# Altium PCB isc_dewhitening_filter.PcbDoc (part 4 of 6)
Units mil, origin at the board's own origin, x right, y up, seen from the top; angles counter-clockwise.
Board outline 8440 x 7000 mil, 6 copper layers (Top Layer, MidLayer1, InternalPlane1, Internal Plane 3, InternalPlane2, Bottom Layer); 550 components, 462 nets, 2189 pads, 795 vias.
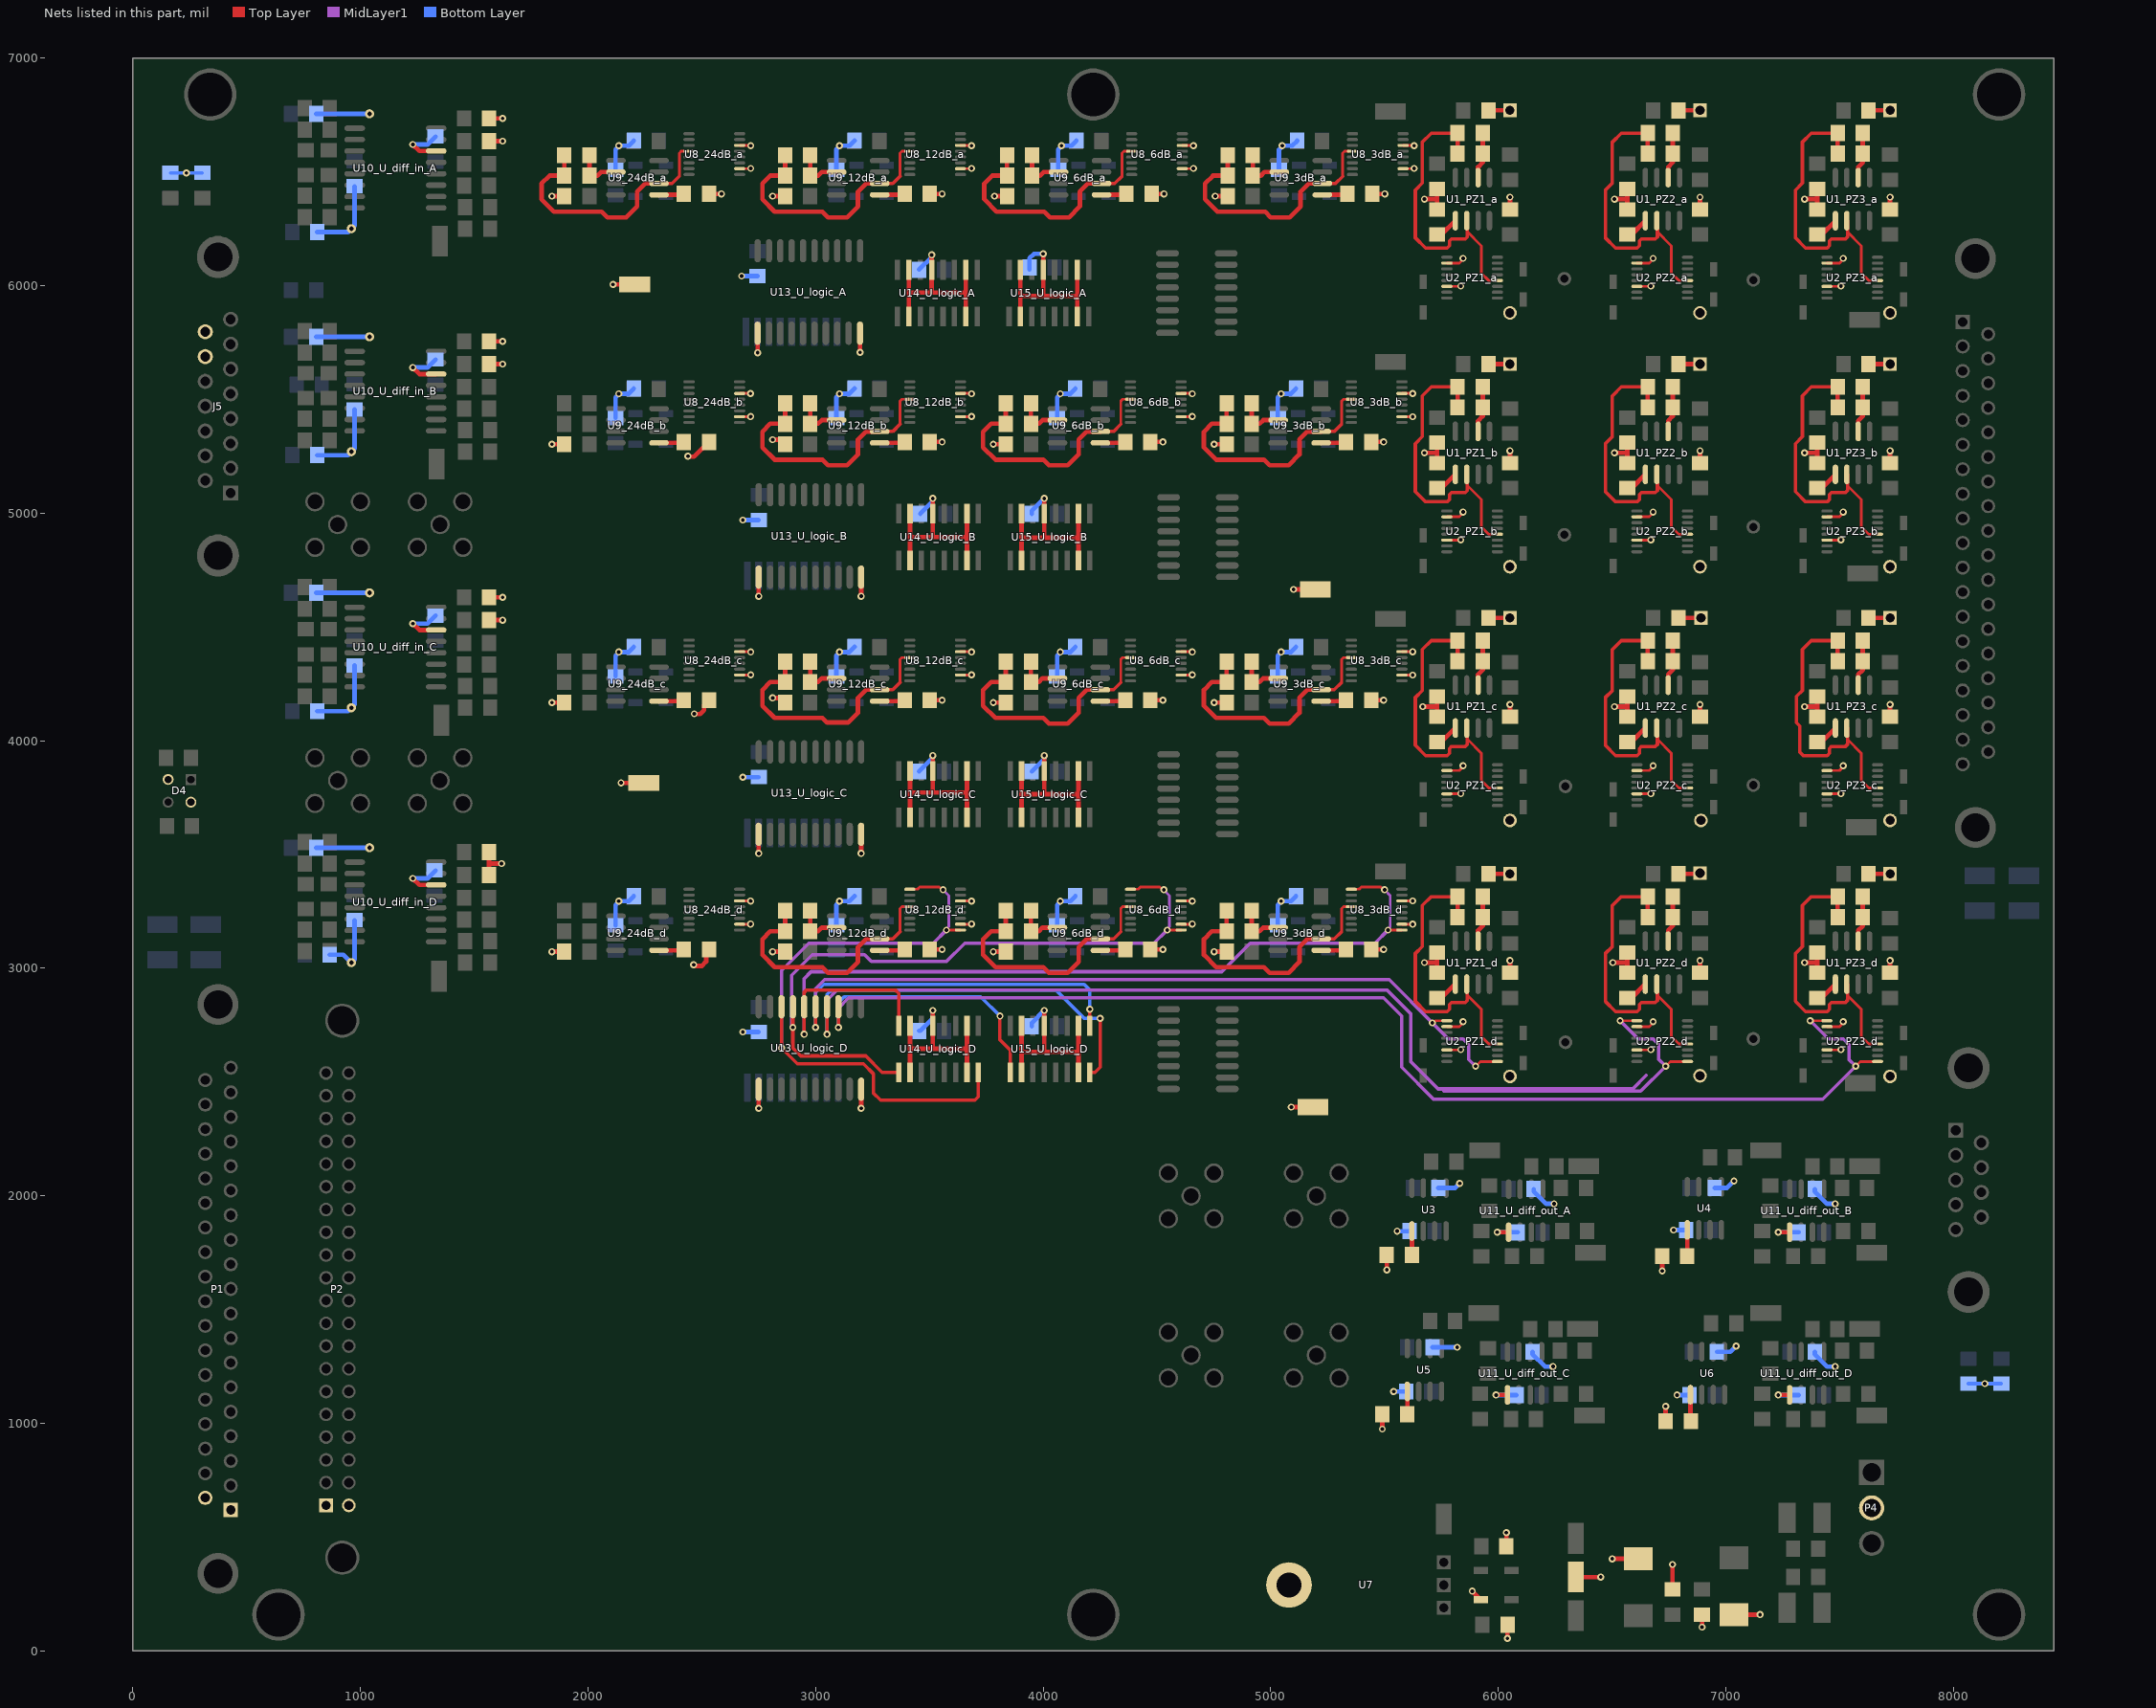
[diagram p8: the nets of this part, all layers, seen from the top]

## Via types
v1: diameter 31, hole 16, Top Layer to Bottom Layer, 794 vias
v2: diameter 45, hole 20, Top Layer to Bottom Layer, 1 vias

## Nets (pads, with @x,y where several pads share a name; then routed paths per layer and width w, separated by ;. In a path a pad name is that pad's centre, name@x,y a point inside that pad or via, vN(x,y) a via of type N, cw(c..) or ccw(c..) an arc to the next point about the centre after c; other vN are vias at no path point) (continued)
D2: U8_12dB_d.1 U8_12dB_d.9 U13_U_logic_D.18 U14_U_logic_D.16 | length 2851.5
  Top Layer w12: U8_12dB_d.9@3413.78,3347.36 3413.95,3347.53 3447.87,3347.53 3457.34,3357 3542.86,3357 3554.86,3345 v1(3560,3345) ; v1(3575,3168.23) U8_12dB_d.1@3636.22,3168.23
  Top Layer w15: U13_U_logic_D.18@2850,2831.1 v1(2850,2650) 2920,2580 3210,2580 3255,2535 3255,2450 3285,2420 3700,2420 3715,2435 U14_U_logic_D.16@3715,2542.64
  MidLayer1 w12: v1(3560,3345) 3585,3320 3585,3183.37 3575,3173.37 v1(3575,3168.23)
  MidLayer1 w15: v1(2850,2650) 2850,2980 2850,2990 2970,3110 3516.77,3110 v1(3575,3168.23)
D3: U8_6dB_d.1 U8_6dB_d.9 U13_U_logic_D.17 U14_U_logic_D.9 | length 3637
  Top Layer w12: U8_6dB_d.9@4383.78,3347.36 4383.95,3347.53 4417.87,3347.53 4427.34,3357 4512.86,3357 4524.86,3345 v1(4530,3345) ; v1(4545,3168.23) U8_6dB_d.1@4606.22,3168.23
  Top Layer w15: U13_U_logic_D.17@2900,2831.1 v1(2900,2740) 2900,2650 2935,2615 3220,2615 3292.36,2542.64 U14_U_logic_D.9@3365,2542.64
  MidLayer1 w12: v1(4530,3345) 4555,3320 4555,3183.37 4545,3173.37 v1(4545,3168.23)
  MidLayer1 w15: v1@2895,2740 2895,2970 2985,3060 3215,3060 3245,3030 3575,3030 3655,3110 4491.77,3110 ; 3940,3110 4486.77,3110 v1(4545,3168.23)
D4: U8_3dB_d.1 U8_3dB_d.9 U13_U_logic_D.16 U14_U_logic_D.8 | length 4625.8
  Top Layer w12: U8_3dB_d.9@5353.78,3347.36 5353.95,3347.53 5387.87,3347.53 5397.34,3357 5482.86,3357 5494.86,3345 v1(5500,3345) ; v1(5515,3168.23) U8_3dB_d.1@5576.22,3168.23
  Top Layer w15: v1(2950,2710) U13_U_logic_D.16@2950,2831.1 2950,2895 2960,2905 3350,2905 3365,2890 U14_U_logic_D.8@3365,2747.36
  MidLayer1 w12: v1(5500,3345) 5525,3320 5525,3183.37 5515,3173.37 v1(5515,3168.23)
  MidLayer1 w15: v1(2950,2710) 2950,2955 2980,2985 4785,2985 4910,3110 ; 4925,3110 4910,3110 ; 5461.77,3110 5456.77,3110 ; v1(5515,3168.23) 5456.77,3110 ; 4910,3110 5456.77,3110 ; 4910,3110 5456.77,3110
D5: U2_PZ1_d.1 U2_PZ1_d.9 U13_U_logic_D.15 U15_U_logic_D.1 | length 5088.1
  Top Layer w12: v1(5710,2760) 5715.14,2760 5724.71,2769.57 U2_PZ1_d.1@5773.78,2769.57 ; v1(5900,2570) 5920.43,2590.43 U2_PZ1_d.9@5996.22,2590.43
  Top Layer w15: v1(3000,2740) U13_U_logic_D.15@3000,2831.1 ; U15_U_logic_D.1@4205,2747.36 v1(4205,2820)
  MidLayer1 w15: v1(3000,2740) 3000,2910 3040,2950 5520,2950 v1(5710,2760) 5780,2690 5845,2690 5870,2665 5870,2600 v1(5900,2570)
  Bottom Layer w15: v1(3000,2740) 3000,2895 3035,2930 4180,2930 4205,2905 v1(4205,2820)
D6: U2_PZ2_d.1 U2_PZ2_d.9 U13_U_logic_D.14 U15_U_logic_D.16 | length 7442.2
  Top Layer w12: v1(6535,2770) 6535.43,2769.57 U2_PZ2_d.1@6608.78,2769.57 ; v1(6735,2570) 6755.43,2590.43 U2_PZ2_d.9@6831.22,2590.43
  Top Layer w15: v1(3050,2710) U13_U_logic_D.14@3050,2831.1 ; U15_U_logic_D.16@4205,2542.64 4227.64,2542.64 4250,2565 v1(4250,2780)
  MidLayer1 w15: v1(3050,2710) 3050,2860 3095,2905 5510,2905 5615,2800 5615,2590 5735,2470 6590,2470 6650,2530 ; 5760,2460 6625,2460 v1(6735,2570) 6705,2600 6705,2665 6680,2690 6615,2690 v1(6535,2770)
  Bottom Layer w15: v1(3050,2710) 3050,2885 3070,2905 4055,2905 4180,2780 v1(4250,2780)
D7: U2_PZ3_d.1 U2_PZ3_d.9 U13_U_logic_D.13 U15_U_logic_D.9 | length 6672.3
  Top Layer w12: v1(7370,2770) 7370.43,2769.57 U2_PZ3_d.1@7443.78,2769.57 ; v1(7570,2570) 7590.43,2590.43 U2_PZ3_d.9@7666.22,2590.43
  Top Layer w15: v1(3100,2740) U13_U_logic_D.13@3100,2831.1 ; v1(3810,2790) 3810,2685 3855,2640 U15_U_logic_D.9@3855,2542.64
  MidLayer1 w15: v1(3100,2740) 3100,2825 3145,2870 5495,2870 5575,2790 5575,2565 5714.61,2425.38 7380.39,2425.38 ; v1(7370,2770) 7450,2690 7515,2690 7540,2665 7540,2600 v1(7570,2570) 7425,2425 7380,2425
  Bottom Layer w15: v1(3100,2740) 3100,2850 3125,2875 3725,2875 v1(3810,2790)
GND: C1_PZ1_a.1 C1_PZ1_b.1 C1_PZ1_c.1 C1_PZ1_d.1 C1_PZ2_a.1 C1_PZ2_b.1 C1_PZ2_c.1 C1_PZ2_d.1 C1_PZ3_a.1 C1_PZ3_b.1 C1_PZ3_c.1 C1_PZ3_d.1 C2_PZ1_a.1 C2_PZ1_b.1 C2_PZ1_c.1 C2_PZ1_d.1 C2_PZ2_a.1 C2_PZ2_b.1 C2_PZ2_c.1 C2_PZ2_d.1 C2_PZ3_a.1 C2_PZ3_b.1 C2_PZ3_c.1 C2_PZ3_d.1 C3_PZ1_a.1 C3_PZ1_b.1 C3_PZ1_c.1 C3_PZ1_d.1 C3_PZ2_a.1 C3_PZ2_b.1 C3_PZ2_c.1 C3_PZ2_d.1 C3_PZ3_a.1 C3_PZ3_b.1 C3_PZ3_c.1 C3_PZ3_d.1 C5_PZ1_a.2 C5_PZ1_b.2 C5_PZ1_c.2 C5_PZ1_d.2 C5_PZ2_a.2 C5_PZ2_b.2 C5_PZ2_c.2 C5_PZ2_d.2 C5_PZ3_a.2 C5_PZ3_b.2 C5_PZ3_c.2 C5_PZ3_d.2 C6.1 C7.1 C8.1 C9.1 C10.1 C11.1 C12.1 C13.1 C14.1 C15.1 C16.1 C17.1 C18.2 C19.2 C20.1 C21.1 C22.2 C23.1 C24_3dB_a.1 C24_3dB_b.1 C24_3dB_c.1 C24_3dB_d.1 C24_6dB_a.1 C24_6dB_b.1 C24_6dB_c.1 C24_6dB_d.1 C24_12dB_a.1 C24_12dB_b.1 C24_12dB_c.1 C24_12dB_d.1 C24_24dB_a.1 C24_24dB_b.1 C24_24dB_c.1 C24_24dB_d.1 C25_3dB_a.1 C25_3dB_b.1 C25_3dB_c.1 C25_3dB_d.1 C25_6dB_a.1 C25_6dB_b.1 C25_6dB_c.1 C25_6dB_d.1 C25_12dB_a.1 C25_12dB_b.1 C25_12dB_c.1 C25_12dB_d.1 C25_24dB_a.1 C25_24dB_b.1 C25_24dB_c.1 C25_24dB_d.1 C26_3dB_a.1 C26_3dB_b.1 C26_3dB_c.1 C26_3dB_d.1 C26_6dB_a.1 C26_6dB_b.1 C26_6dB_c.1 C26_6dB_d.1 C26_12dB_a.1 C26_12dB_b.1 C26_12dB_c.1 C26_12dB_d.1 C26_24dB_a.1 C26_24dB_b.1 C26_24dB_c.1 C26_24dB_d.1 C28_U_diff_in_A.2 C28_U_diff_in_B.2 C28_U_diff_in_C.2 C28_U_diff_in_D.2 C29_U_diff_in_A.2 C29_U_diff_in_B.2 C29_U_diff_in_C.2 C29_U_diff_in_D.2 C30_U_diff_out_A.2 C30_U_diff_out_B.2 C30_U_diff_out_C.2 C30_U_diff_out_D.2 C31_U_diff_out_A.2 C31_U_diff_out_B.2 C31_U_diff_out_C.2 C31_U_diff_out_D.2 C32_U_logic_A.1 C32_U_logic_B.1 C32_U_logic_C.1 C32_U_logic_D.1 C33_U_logic_A.1 C33_U_logic_B.1 C33_U_logic_C.1 C33_U_logic_D.1 C34.1 C35.1 C36_U_logic_A.1 C36_U_logic_B.1 C36_U_logic_C.1 C36_U_logic_D.1 C37_U_diff_in_A.1 C37_U_diff_in_B.1 C37_U_diff_in_C.1 C37_U_diff_in_D.1 D4.2 D4.3 D5.1 J5.14 J5.15 P1.1 P1.20 P2.1 P2.2 P4.2 pad.0@1040,3530 pad.0@1040,4650 pad.0@1040,5775 pad.0@1040,6755 pad.1@960,3025 pad.1@960,4145 pad.1@960,5270 pad.1@960,6250 R12_3dB_a.1 R12_3dB_b.1 R12_3dB_c.1 R12_3dB_d.1 R12_6dB_a.1 R12_6dB_b.1 R12_6dB_c.1 R12_6dB_d.1 R12_12dB_a.1 R12_12dB_b.1 R12_12dB_c.1 R12_12dB_d.1 R12_24dB_a.1 R12_24dB_b.1 R12_24dB_c.1 R12_24dB_d.1 R14_U_diff_in_A.1 R14_U_diff_in_B.1 R14_U_diff_in_C.1 R14_U_diff_in_D.1 R16_U_diff_in_A.2 R16_U_diff_in_B.2 R16_U_diff_in_C.2 R16_U_diff_in_D.2 R22_U_diff_in_A.2 R22_U_diff_in_B.2 R22_U_diff_in_C.2 R22_U_diff_in_D.2 R34.1 R37.1 TP4.1 TP9.1 TP10.1 TP11.1 TP12.1 U2_PZ1_a.2 U2_PZ1_a.6 U2_PZ1_b.2 U2_PZ1_b.6 U2_PZ1_c.2 U2_PZ1_c.6 U2_PZ1_d.2 U2_PZ1_d.6 U2_PZ2_a.2 U2_PZ2_a.6 U2_PZ2_b.2 U2_PZ2_b.6 U2_PZ2_c.2 U2_PZ2_c.6 U2_PZ2_d.2 U2_PZ2_d.6 U2_PZ3_a.2 U2_PZ3_a.6 U2_PZ3_b.2 U2_PZ3_b.6 U2_PZ3_c.2 U2_PZ3_c.6 U2_PZ3_d.2 U2_PZ3_d.6 U7.4 U8_3dB_a.2 U8_3dB_a.6 U8_3dB_b.2 U8_3dB_b.6 U8_3dB_c.2 U8_3dB_c.6 U8_3dB_d.2 U8_3dB_d.6 U8_6dB_a.2 U8_6dB_a.6 U8_6dB_b.2 U8_6dB_b.6 U8_6dB_c.2 U8_6dB_c.6 U8_6dB_d.2 U8_6dB_d.6 U8_12dB_a.2 U8_12dB_a.6 U8_12dB_b.2 U8_12dB_b.6 U8_12dB_c.2 U8_12dB_c.6 U8_12dB_d.2 U8_12dB_d.6 U8_24dB_a.2 U8_24dB_a.6 U8_24dB_b.2 U8_24dB_b.6 U8_24dB_c.2 U8_24dB_c.6 U8_24dB_d.2 U8_24dB_d.6 U10_U_diff_in_A.14 U10_U_diff_in_B.14 U10_U_diff_in_C.14 U10_U_diff_in_D.14 U11_U_diff_out_A.5 U11_U_diff_out_B.5 U11_U_diff_out_C.5 U11_U_diff_out_D.5 U13_U_logic_A.1 U13_U_logic_A.10 U13_U_logic_B.1 U13_U_logic_B.10 U13_U_logic_C.1 U13_U_logic_C.10 U13_U_logic_D.1 U13_U_logic_D.10 U14_U_logic_A.2 U14_U_logic_A.5 U14_U_logic_A.7 U14_U_logic_A.10 U14_U_logic_A.15 U14_U_logic_B.2 U14_U_logic_B.5 U14_U_logic_B.7 U14_U_logic_B.10 U14_U_logic_B.15 U14_U_logic_C.2 U14_U_logic_C.5 U14_U_logic_C.7 U14_U_logic_C.10 U14_U_logic_C.15 U14_U_logic_D.2 U14_U_logic_D.5 U14_U_logic_D.7 U14_U_logic_D.10 U14_U_logic_D.15 U15_U_logic_A.2 U15_U_logic_A.5 U15_U_logic_A.7 U15_U_logic_A.10 U15_U_logic_A.15 U15_U_logic_B.2 U15_U_logic_B.5 U15_U_logic_B.7 U15_U_logic_B.10 U15_U_logic_B.15 U15_U_logic_C.2 U15_U_logic_C.5 U15_U_logic_C.7 U15_U_logic_C.10 U15_U_logic_C.15 U15_U_logic_D.2 U15_U_logic_D.5 U15_U_logic_D.7 U15_U_logic_D.10 U15_U_logic_D.15 | length 26300.4
  Top Layer w12: U8_24dB_d.2@2666.22,3193.82 v1(2713.82,3193.82) v1(2715,3195) ; U8_24dB_d.6@2666.22,3296.18 v1(2713.82,3296.18) v1(2715,3295) ; U8_24dB_c.2@2666.22,4288.82 2713.82,4288.82 v1(2715,4290) ; U8_24dB_c.6@2666.22,4391.18 2713.82,4391.18 v1(2715,4390) ; U8_24dB_b.2@2666.22,5423.82 v1(2713.82,5423.82) v1(2715,5425) ; U8_24dB_b.6@2666.22,5526.18 v1(2713.82,5526.18) v1@2715,5525 ; U8_24dB_a.2@2666.22,6513.82 2713.82,6513.82 v1(2715,6515) ; U8_24dB_a.6@2666.22,6616.18 2713.82,6616.18 v1(2715,6615) ; U8_12dB_d.2@3636.22,3193.82 3683.82,3193.82 v1(3685,3195) ; U8_12dB_d.6@3636.22,3296.18 3683.82,3296.18 v1(3685,3295) ; U8_12dB_c.2@3636.22,4288.82 3683.82,4288.82 v1(3685,4290) ; U8_12dB_c.6@3636.22,4391.18 3683.82,4391.18 v1(3685,4390) ; U8_12dB_b.2@3636.22,5423.82 3683.82,5423.82 v1(3685,5425) ; U8_12dB_b.6@3636.22,5526.18 3683.82,5526.18 v1(3685,5525) ; U8_12dB_a.2@3636.22,6513.82 3683.82,6513.82 v1(3685,6515) ; U8_12dB_a.6@3636.22,6616.18 3683.82,6616.18 v1(3685,6615) ; U8_6dB_d.2@4606.22,3193.82 4653.82,3193.82 v1(4655,3195) ; U8_6dB_d.6@4606.22,3296.18 4653.82,3296.18 v1(4655,3295) ; U8_6dB_c.2@4606.22,4288.82 4653.82,4288.82 v1(4655,4290) ; U8_6dB_c.6@4606.22,4391.18 4653.82,4391.18 v1(4655,4390) ; U8_6dB_b.2@4606.22,5423.82 4653.82,5423.82 v1(4655,5425) ; U8_6dB_b.6@4606.22,5526.18 4653.82,5526.18 v1(4655,5525) ; U8_6dB_a.2@4611.22,6513.82 4658.82,6513.82 v1(4660,6515) ; U8_6dB_a.6@4611.22,6616.18 4658.82,6616.18 v1(4660,6615) ; U8_3dB_d.2@5576.22,3193.82 v1(5623.82,3193.82) ; U8_3dB_d.6@5576.22,3296.18 v1(5623.82,3296.18) ; U8_3dB_c.2@5576.22,4288.82 v1(5623.82,4288.82) ; U8_3dB_c.6@5576.22,4391.18 v1(5623.82,4391.18) ; U8_3dB_b.2@5576.22,5423.82 v1(5623.82,5423.82) ; U8_3dB_b.6@5576.22,5526.18 v1(5623.82,5526.18) ; U8_3dB_a.2@5581.22,6513.82 5628.82,6513.82 v1(5630,6515) ; U8_3dB_a.6@5581.22,6616.18 5628.82,6616.18 v1(5630,6615) ; U2_PZ1_d.6@5773.78,2641.61 v1@5833.98,2641.61 ; U2_PZ1_d.2@5773.78,2743.98 5828.59,2743.98 5845,2760.39 v1(5845,2765) ; U2_PZ1_c.6@5773.78,3766.61 v1@5833.98,3766.61 ; U2_PZ1_c.2@5773.78,3868.98 5828.59,3868.98 5845,3885.39 v1(5845,3890) ; U2_PZ1_b.6@5773.78,4881.61 v1@5833.98,4881.61 ; U2_PZ1_b.2@5773.78,4983.98 5828.59,4983.98 5845,5000.39 v1(5845,5005) ; U2_PZ1_a.6@5773.78,5996.61 v1@5833.98,5996.61 ; U2_PZ1_a.2@5773.78,6098.98 5828.59,6098.98 5845,6115.39 v1(5845,6120) ; U2_PZ2_d.6@6608.78,2641.61 v1@6668.98,2641.61 ; U2_PZ2_d.2@6608.78,2743.98 6663.59,2743.98 6680,2760.39 v1(6680,2765) ; U2_PZ2_c.6@6608.78,3766.61 v1@6668.98,3766.61 ; U2_PZ2_c.2@6608.78,3868.98 6663.59,3868.98 6680,3885.39 v1(6680,3890) ; U2_PZ2_b.6@6608.78,4881.61 v1@6668.98,4881.61 ; U2_PZ2_b.2@6608.78,4983.98 6663.59,4983.98 6680,5000.39 v1(6680,5005) ; U2_PZ2_a.6@6608.78,5996.61 v1@6668.98,5996.61 ; U2_PZ2_a.2@6608.78,6098.98 6663.59,6098.98 6680,6115.39 v1(6680,6120) ; U2_PZ3_d.6@7443.78,2641.61 v1@7503.98,2641.61 ; U2_PZ3_d.2@7443.78,2743.98 7498.59,2743.98 7515,2760.39 v1(7515,2765) ; U2_PZ3_c.6@7443.78,3766.61 v1@7503.98,3766.61 ; U2_PZ3_c.2@7443.78,3868.98 7498.59,3868.98 7515,3885.39 v1(7515,3890) ; U2_PZ3_b.6@7443.78,4881.61 v1@7503.98,4881.61 ; U2_PZ3_b.2@7443.78,4983.98 7498.59,4983.98 7515,5000.39 v1(7515,5005) ; U2_PZ3_a.6@7443.78,5996.61 v1@7503.98,5996.61 ; U2_PZ3_a.2@7443.78,6098.98 7498.59,6098.98 7515,6115.39 v1(7515,6120)
  Top Layer w20: v1(1230,3395) 1258.5,3366.5 U10_U_diff_in_D.14@1332.8,3366.5 ; v1(1230,4515) 1258.5,4486.5 U10_U_diff_in_C.14@1332.8,4486.5 ; v1(1230,5640) 1258.5,5611.5 U10_U_diff_in_B.14@1332.8,5611.5 ; v1(1230,6620) 1258.5,6591.5 U10_U_diff_in_A.14@1332.8,6591.5 ; R16_U_diff_in_D.2@1565.12,3410 1565.12,3460 ; C37_U_diff_in_D.1@1565.12,3510 1565.12,3460 ; R16_U_diff_in_C.2@1565.12,4530 v1(1625,4530) ; C37_U_diff_in_C.1@1565.12,4630 v1(1625,4630) ; R16_U_diff_in_B.2@1565.12,5655 v1(1625,5655) ; C37_U_diff_in_B.1@1565.12,5755 v1(1625,5755) ; R16_U_diff_in_A.2@1565.12,6635 v1(1625,6635) ; C37_U_diff_in_A.1@1565.12,6735 v1(1625,6735) ; v1(1620,3460) 1565.12,3460 ; v1(1841,3073) R12_24dB_d.1@1895.88,3073 R12_24dB_d.1@1876,3073 ; v1(1841,4168) R12_24dB_c.1@1895.88,4168 R12_24dB_c.1@1876,4168 ; v1(1841,5303) R12_24dB_b.1@1895.88,5303 R12_24dB_b.1@1876,5303 ; v1(1841,6393) R12_24dB_a.1@1895.88,6393 R12_24dB_a.1@1876,6393 ; v1(2110,6005) TP9.1@2205,6005 ; v1(2145,3815) TP11.1@2245,3815 ; v1(2439.17,5250.83) 2442.14,5250.83 2444.86,5248.11 2466.23,5248.11 2505.68,5287.57 2509.62,5287.57 2531.12,5309.06 C25_24dB_b.1@2531.12,5313 ; v1(2464.17,3015.83) 2467.14,3015.83 2472.98,3010 2500,3010 2519.28,3029.28 2519.28,3071.16 C25_24dB_d.1@2531.12,3083 ; v1(2466.67,4118.33) 2467.83,4117.17 2492.17,4117.17 2509.62,4134.62 2509.62,4156.5 C25_24dB_c.1@2531.12,4178 ; C25_24dB_a.1@2531.12,6403 v1(2586,6403) ; v1(2745,5705) U13_U_logic_A.1@2745,5790.9 ; v1(2750,2385) U13_U_logic_D.1@2750,2468.9 ; v1(2750,3505) U13_U_logic_C.1@2750,3588.9 ; v1(2750,4635) U13_U_logic_B.1@2750,4718.9 ; v1(2811,3073) R12_12dB_d.1@2865.88,3073 R12_12dB_d.1@2846,3073 ; v1(2811,4188) R12_12dB_c.1@2865.88,4188 ; v1(2811,5323) R12_12dB_b.1@2865.88,5323 ; v1(2811,6393) R12_12dB_a.1@2865.88,6393 R12_12dB_a.1@2846,6393 ; v1(3195,5707) U13_U_logic_A.10@3195,5790.9 ; v1(3200,2385) U13_U_logic_D.10@3200,2468.9 ; v1(3200,3505) U13_U_logic_C.10@3200,3588.9 ; v1(3200,4635) U13_U_logic_B.10@3200,4718.9 ; U14_U_logic_A.10@3410,5864.64 3410,5969 ; U14_U_logic_A.7@3410,6069.36 3410,5969 ; U14_U_logic_D.10@3415,2542.64 3415,2647 ; U14_U_logic_D.7@3415,2747.36 3415,2647 ; U14_U_logic_C.10@3415,3662.64 U14_U_logic_C.7@3415,3867.36 ; U14_U_logic_B.10@3415,4792.64 3415,4895 ; U14_U_logic_B.7@3415,4997.36 3415,4895 ; 3417,3772 3665,3772 ; C25_12dB_d.1@3501.12,3083 v1(3556,3083) ; C25_12dB_c.1@3501.12,4178 v1(3556,4178) ; C25_12dB_b.1@3501.12,5313 v1(3556,5313) ; C25_12dB_a.1@3501.12,6403 v1(3556,6403) ; v1(3510,6135) U14_U_logic_A.5@3510,6069.36 3510,5969 ; v1(3515,2815) U14_U_logic_D.5@3515,2747.36 3515,2647 ; 3515,3773 U14_U_logic_C.5@3515,3867.36 v1(3515,3935) ; 3515,4898 U14_U_logic_B.5@3515,4997.36 v1(3515,5065) ; 3658,5969 3510,5969 ; U14_U_logic_A.15@3660,5864.64 U14_U_logic_A.2@3660,6069.36 ; 3663,2647 3515,2647 ; U14_U_logic_D.15@3665,2542.64 U14_U_logic_D.2@3665,2747.36 ; U14_U_logic_C.15@3665,3662.64 3665,3772 ; U14_U_logic_C.2@3665,3867.36 3665,3772 ; U14_U_logic_B.15@3665,4792.64 3665,4895 ; U14_U_logic_B.2@3665,4997.36 3665,4895 ; v1(3781,3073) R12_6dB_d.1@3835.88,3073 R12_6dB_d.1@3816,3073 ; v1(3781,4168) R12_6dB_c.1@3835.88,4168 ; v1(3781,5303) R12_6dB_b.1@3835.88,5303 R12_6dB_b.1@3816,5303 ; v1(3786,6393) R12_6dB_a.1@3840.88,6393 R12_6dB_a.1@3821,6393 ; U15_U_logic_A.10@3900,5864.64 3900,5955 ; U15_U_logic_A.7@3900,6069.36 3900,5955 ; U15_U_logic_D.10@3905,2542.64 3905,2633 ; U15_U_logic_D.7@3905,2747.36 3905,2633 ; U15_U_logic_C.10@3905,3662.64 3905,3765 ; U15_U_logic_C.7@3905,3867.36 3905,3765 ; U15_U_logic_B.10@3905,4792.64 3905,4892 ; U15_U_logic_B.7@3905,4997.36 3905,4892 ; 4000,5957 U15_U_logic_A.5@4000,6069.36 v1(4000,6140) ; 4005,2634 U15_U_logic_D.5@4005,2747.36 v1(4005,2815) ; 4005,3768 U15_U_logic_C.5@4005,3867.36 v1(4005,3935) ; 4005,4894 U15_U_logic_B.5@4005,4997.36 v1(4005,5065) ; 4147,5955 3900,5955 ; U15_U_logic_A.15@4150,5864.64 U15_U_logic_A.2@4150,6069.36 ; 4151,3765 3905,3765 ; 4152,4892 3905,4892 ; U15_U_logic_D.15@4155,2542.64 4155,2633 ; U15_U_logic_D.2@4155,2747.36 4155,2633 ; U15_U_logic_C.15@4155,3662.64 U15_U_logic_C.2@4155,3867.36 ; U15_U_logic_B.15@4155,4792.64 U15_U_logic_B.2@4155,4997.36 ; C25_6dB_d.1@4471.12,3083 v1(4526,3083) ; C25_6dB_c.1@4471.12,4178 v1(4526,4178) ; C25_6dB_b.1@4471.12,5313 v1(4526,5313) ; C25_6dB_a.1@4476.12,6403 v1(4531,6403) ; v1(4751,3073) R12_3dB_d.1@4805.88,3073 R12_3dB_d.1@4786,3073 ; v1(4751,4168) R12_3dB_c.1@4805.88,4168 R12_3dB_c.1@4786,4168 ; v1(4751,5303) R12_3dB_b.1@4805.88,5303 R12_3dB_b.1@4786,5303 ; v1(4756,6393) R12_3dB_a.1@4810.88,6393 R12_3dB_a.1@4791,6393 ; v1(5090,2390) TP12.1@5185,2390 ; v1(5100,4665) TP10.1@5195,4665 ; C25_3dB_d.1@5441.12,3083 v1(5496,3083) ; C25_3dB_c.1@5441.12,4178 v1(5496,4178) ; C25_3dB_b.1@5441.12,5313 v1(5496,5313) ; C25_3dB_a.1@5446.12,6403 v1(5501,6403) ; C13.1@5489.88,1040 5490,1039.88 v1(5490,975) ; C7.1@5509.88,1740 5510,1739.88 v1(5510,1675) ; v1(5668,4150) 5731,4150 ; v1(5675,3025) 5731,3025 ; v1(5675,5265) 5731,5265 ; v1(5675,6380) 5731,6380 ; C2_PZ1_d.1@5731,2980.12 5731,3025 ; C1_PZ1_d.1@5731,3069.88 5731,3025 ; C2_PZ1_c.1@5731,4105.12 5731,4150 ; C1_PZ1_c.1@5731,4194.88 5731,4150 ; C2_PZ1_b.1@5731,5220.12 5731,5265 ; C1_PZ1_b.1@5731,5309.88 5731,5265 ; C2_PZ1_a.1@5731,6335.12 5731,6380 ; C1_PZ1_a.1@5731,6424.88 5731,6380 ; v1(5885,263.07) D5.1@5923.07,225 ; v1(5990,1125) 5990.51,1125.51 U11_U_diff_out_C.5@6040,1125.51 ; v1(5995,1840) 5995.51,1840.51 U11_U_diff_out_A.5@6045,1840.51 ; C21.1@6035.12,460 v1(6035.12,519.88) ; v1(6040.12,55.12) C20.1@6040.12,115 ; v1@6050,3035 v1(6051,3034) C3_PZ1_d.1@6051,2980.12 ; v1@6050,4160 v1(6051,4159) C3_PZ1_c.1@6051,4105.12 ; v1@6050,5275 v1(6051,5274) C3_PZ1_b.1@6051,5220.12 ; v1@6050,6390 v1(6051,6389) C3_PZ1_a.1@6051,6335.12 ; TP4.1@6340,325 v1(6450,325) ; v1(6500,405) C23.1@6615,405 ; v1(6503,3025) 6566,3025 ; v1(6510,4150) 6566,4150 ; v1(6510,5265) 6566,5265 ; v1(6510,6380) 6566,6380 ; C2_PZ2_d.1@6566,2980.12 6566,3025 ; C1_PZ2_d.1@6566,3069.88 6566,3025 ; C2_PZ2_c.1@6566,4105.12 6566,4150 ; C1_PZ2_c.1@6566,4194.88 6566,4150 ; C2_PZ2_b.1@6566,5220.12 6566,5265 ; C1_PZ2_b.1@6566,5309.88 6566,5265 ; C2_PZ2_a.1@6566,6335.12 6566,6380 ; C1_PZ2_a.1@6566,6424.88 6566,6380 ; C10.1@6719.88,1735 6720,1734.88 v1(6720,1670) ; C16.1@6734.88,1010 v1@6734.88,1074.88 ; C22.2@6765,270.12 v1(6765,380) ; v1@6885,3035 v1(6886,3034) C3_PZ2_d.1@6886,2980.12 ; v1@6885,4160 v1(6886,4159) C3_PZ2_c.1@6886,4105.12 ; v1@6885,5275 v1(6886,5274) C3_PZ2_b.1@6886,5220.12 ; v1@6885,6390 v1(6886,6389) C3_PZ2_a.1@6886,6335.12 ; v1(6895,105) C19.2@6895,159.88 ; C18.2@7035,160 v1(7150,160) ; v1(7230,1125) 7230.51,1125.51 U11_U_diff_out_D.5@7280,1125.51 ; v1(7230,1840) 7230.51,1840.51 U11_U_diff_out_B.5@7280,1840.51 ; v1(7345,3025) 7401,3025 ; v1(7345,4150) 7401,4150 ; v1(7345,5265) 7401,5265 ; v1(7345,6380) 7401,6380 ; C2_PZ3_d.1@7401,2980.12 7401,3025 ; C1_PZ3_d.1@7401,3069.88 7401,3025 ; C2_PZ3_c.1@7401,4105.12 7401,4150 ; C1_PZ3_c.1@7401,4194.88 7401,4150 ; C2_PZ3_b.1@7401,5220.12 7401,5265 ; C1_PZ3_b.1@7401,5309.88 7401,5265 ; C2_PZ3_a.1@7401,6335.12 7401,6380 ; C1_PZ3_a.1@7401,6424.88 7401,6380 ; v1@7720,3035 v1(7721,3034) C3_PZ3_d.1@7721,2980.12 ; v1@7720,4160 v1(7721,4159) C3_PZ3_c.1@7721,4105.12 ; v1@7720,6390 v1(7721,6389) C3_PZ3_a.1@7721,6335.12 ; C3_PZ3_b.1@7721,5220.12 v1(7721,5274) ; 3410,5969 3510,5969 ; 3415,2647 3515,2647 ; 3415,4895 3665,4895 ; 3905,2633 4155,2633
  Bottom Layer w15: C34.1@165,6495.12 R34.1@304.88,6495.12 ; C35.1@8065,1174.88 R37.1@8210,1174.88
  Bottom Layer w20: R22_U_diff_in_D.2@805.12,3530 pad.0@1040,3530 ; R22_U_diff_in_C.2@805.12,4650 pad.0@1040,4650 ; R22_U_diff_in_B.2@805.12,5775 pad.0@1040,5775 ; R22_U_diff_in_A.2@805.12,6755 pad.0@1040,6755 ; R14_U_diff_in_C.1@810.12,4130 945,4130 974.53,4159.53 C28_U_diff_in_C.2@974.53,4331.38 ; R14_U_diff_in_B.1@810.12,5255 945,5255 974.53,5284.53 C28_U_diff_in_B.2@974.53,5456.38 ; R14_U_diff_in_A.1@810.12,6235 945,6235 974.53,6264.53 C28_U_diff_in_A.2@974.53,6436.38 ; R14_U_diff_in_D.1@865.12,3060 925,3060 pad.1@960,3025 974.53,3039.53 C28_U_diff_in_D.2@974.53,3211.38 ; v1(1230,3395) 1294.88,3395 C29_U_diff_in_D.2@1330,3430.12 ; v1(1230,4515) 1294.88,4515 C29_U_diff_in_C.2@1330,4550.12 ; v1(1230,5640) 1294.88,5640 C29_U_diff_in_B.2@1330,5675.12 ; v1(1230,6620) 1294.88,6620 C29_U_diff_in_A.2@1330,6655.12 ; C24_24dB_d.1@2121,3188.12 2121,3278.02 2135,3292.02 v1(2135,3295) 2179.39,3295 2200.88,3316.5 C26_24dB_d.1@2200.88,3318 ; C24_24dB_c.1@2121,4283.12 2121,4373.02 2135,4387.02 v1(2135,4390) 2179.39,4390 2200.88,4411.5 C26_24dB_c.1@2200.88,4413 ; C24_24dB_b.1@2121,5418.12 2121,5508.02 2135,5522.02 v1(2135,5525) 2179.39,5525 2200.88,5546.5 C26_24dB_b.1@2200.88,5548 ; C24_24dB_a.1@2121,6508.12 2121,6598.02 2135,6612.02 v1(2135,6615) 2179.39,6615 2200.88,6636.5 C26_24dB_a.1@2200.88,6638 ; v1@2675,6041.88 C33_U_logic_A.1@2745,6041.88 ; v1@2680,2719.88 C33_U_logic_D.1@2750,2719.88 ; v1@2680,3839.88 C33_U_logic_C.1@2750,3839.88 ; v1@2680,4969.88 C33_U_logic_B.1@2750,4969.88 ; C24_12dB_d.1@3091,3188.12 3091,3278.02 3105,3292.02 v1(3105,3295) 3149.39,3295 3170.88,3316.5 C26_12dB_d.1@3170.88,3318 ; C24_12dB_c.1@3091,4283.12 3091,4373.02 3105,4387.02 v1(3105,4390) 3149.39,4390 3170.88,4411.5 C26_12dB_c.1@3170.88,4413 ; C24_12dB_b.1@3091,5418.12 3091,5508.02 3105,5522.02 v1(3105,5525) 3149.39,5525 3170.88,5546.5 C26_12dB_b.1@3170.88,5548 ; C24_12dB_a.1@3091,6508.12 3091,6598.02 3105,6612.02 v1(3105,6615) 3149.39,6615 3170.88,6636.5 C26_12dB_a.1@3170.88,6638 ; C32_U_logic_D.1@3454.88,2725 3460,2725 3515,2780 v1(3515,2815) ; C32_U_logic_C.1@3454.88,3865 3515,3925.12 v1(3515,3935) ; C32_U_logic_A.1@3454.88,6070 3510,6125.12 v1(3510,6135) ; C32_U_logic_B.1@3459.88,4997.36 3515,5052.48 v1(3515,5065) ; C36_U_logic_A.1@3939.88,6070 3939.88,6119.88 3960,6140 v1(4000,6140) ; C36_U_logic_D.1@3949.88,2745 3949.88,2759.88 v1(4005,2815) ; C36_U_logic_C.1@3949.88,3865 4005,3920.12 v1(4005,3935) ; C36_U_logic_B.1@3949.88,4997.36 3949.88,5009.88 v1(4005,5065) ; C24_6dB_d.1@4061,3188.12 4061,3278.02 4075,3292.02 v1(4075,3295) 4119.39,3295 4140.88,3316.5 C26_6dB_d.1@4140.88,3318 ; C24_6dB_c.1@4061,4283.12 4061,4373.02 4075,4387.02 v1(4075,4390) 4119.39,4390 4140.88,4411.5 C26_6dB_c.1@4140.88,4413 ; C24_6dB_b.1@4061,5418.12 4061,5508.02 4075,5522.02 v1(4075,5525) 4119.39,5525 4140.88,5546.5 C26_6dB_b.1@4140.88,5548 ; C24_6dB_a.1@4066,6508.12 4066,6598.02 4080,6612.02 v1(4080,6615) 4124.39,6615 4145.88,6636.5 C26_6dB_a.1@4145.88,6638 ; C24_3dB_d.1@5031,3188.12 5031,3278.02 5045,3292.02 v1(5045,3295) 5089.39,3295 5110.88,3316.5 C26_3dB_d.1@5110.88,3318 ; C24_3dB_c.1@5031,4283.12 5031,4373.02 5045,4387.02 v1(5045,4390) 5089.39,4390 5110.88,4411.5 C26_3dB_c.1@5110.88,4413 ; C24_3dB_b.1@5031,5418.12 5031,5508.02 5045,5522.02 v1(5045,5525) 5089.39,5525 5110.88,5546.5 C26_3dB_b.1@5110.88,5548 ; C24_3dB_a.1@5036,6508.12 5036,6598.02 5050,6612.02 v1(5050,6615) 5094.39,6615 5115.88,6636.5 C26_3dB_a.1@5115.88,6638 ; v1@5535,1135 v1(5540,1140) C14.1@5594.88,1140 ; v1(5555,1845) C8.1@5609.88,1845 ; C12.1@5710.12,1335 v1(5819,1335) ; C6.1@5735.12,2035 5810,2035 v1(5830,2055) ; v1(5990,1125) C30_U_diff_out_C.2@6079.88,1125 ; v1(5995,1840) C30_U_diff_out_A.2@6084.88,1840 ; C31_U_diff_out_C.2@6150.12,1315 6150.12,1304.88 6205,1250 v1(6240,1250) ; C31_U_diff_out_A.2@6155.12,2030 6155.12,2019.88 6210,1965 v1(6245,1965) ; v1(6770,1850) C11.1@6824.88,1850 ; v1(6785,1125) C17.1@6839.88,1125 ; C9.1@6950.12,2035 7005,2035 v1(7035,2065) ; C15.1@6960.12,1315 7020,1315 v1(7045,1340) ; v1(7230,1125) C30_U_diff_out_D.2@7319.88,1125 ; v1(7230,1840) C30_U_diff_out_B.2@7319.88,1840 ; C31_U_diff_out_D.2@7390.12,1315 7390.12,1304.88 7445,1250 v1(7480,1250) ; C31_U_diff_out_B.2@7390.12,2030 7390.12,2019.88 7445,1965 v1(7480,1965)
  other v1: 6735,1075 8137.5,1174.88 5835,2642.64 6670,2642.64 7505,2642.64 2680,2720 5835,3767.64 6670,3767.64 7505,3767.64 2680,3840 5835,4882.64 6670,4882.64 7505,4882.64 2680,4970 5835,5997.64 6670,5997.64 7505,5997.64 2675,6042 235.12,6494.88
NetC2_PZ1_a_2: C2_PZ1_a.2 U1_PZ1_a.5 | length 105.1
  Top Layer w20: C2_PZ1_a.2@5731,6224.88 5750.37,6224.88 U1_PZ1_a.5@5811,6285.51
NetC2_PZ1_b_2: C2_PZ1_b.2 U1_PZ1_b.5 | length 105.1
  Top Layer w20: C2_PZ1_b.2@5731,5109.88 5750.37,5109.88 U1_PZ1_b.5@5811,5170.51
NetC2_PZ1_c_2: C2_PZ1_c.2 U1_PZ1_c.5 | length 105.1
  Top Layer w20: C2_PZ1_c.2@5731,3994.88 5750.37,3994.88 U1_PZ1_c.5@5811,4055.51
NetC2_PZ1_d_2: C2_PZ1_d.2 U1_PZ1_d.5 | length 105.1
  Top Layer w20: C2_PZ1_d.2@5731,2869.88 5750.37,2869.88 U1_PZ1_d.5@5811,2930.51
NetC2_PZ2_a_2: C2_PZ2_a.2 U1_PZ2_a.5 | length 105.1
  Top Layer w20: C2_PZ2_a.2@6566,6224.88 6585.37,6224.88 U1_PZ2_a.5@6646,6285.51
NetC2_PZ2_b_2: C2_PZ2_b.2 U1_PZ2_b.5 | length 105.1
  Top Layer w20: C2_PZ2_b.2@6566,5109.88 6585.37,5109.88 U1_PZ2_b.5@6646,5170.51
NetC2_PZ2_c_2: C2_PZ2_c.2 U1_PZ2_c.5 | length 105.1
  Top Layer w20: C2_PZ2_c.2@6566,3994.88 6585.37,3994.88 U1_PZ2_c.5@6646,4055.51
NetC2_PZ2_d_2: C2_PZ2_d.2 U1_PZ2_d.5 | length 105.1
  Top Layer w20: C2_PZ2_d.2@6566,2869.88 6585.37,2869.88 U1_PZ2_d.5@6646,2930.51
NetC2_PZ3_a_2: C2_PZ3_a.2 U1_PZ3_a.5 | length 105.1
  Top Layer w20: C2_PZ3_a.2@7401,6224.88 7420.37,6224.88 U1_PZ3_a.5@7481,6285.51
NetC2_PZ3_b_2: C2_PZ3_b.2 U1_PZ3_b.5 | length 105.1
  Top Layer w20: C2_PZ3_b.2@7401,5109.88 7420.37,5109.88 U1_PZ3_b.5@7481,5170.51
NetC2_PZ3_c_2: C2_PZ3_c.2 U1_PZ3_c.5 | length 105.1
  Top Layer w20: C2_PZ3_c.2@7401,3994.88 7420.37,3994.88 U1_PZ3_c.5@7481,4055.51
NetC2_PZ3_d_2: C2_PZ3_d.2 U1_PZ3_d.5 | length 105.1
  Top Layer w20: C2_PZ3_d.2@7401,2869.88 7420.37,2869.88 U1_PZ3_d.5@7481,2930.51
NetC4_PZ1_a_1: C4_PZ1_a.1 R1_PZ1_a.2 U1_PZ1_a.2 | length 218.6
  Top Layer w20: U1_PZ1_a.2@5911,6474.49 5911,6521 5931.12,6541.12 C4_PZ1_a.1@5931.12,6684.76
NetC4_PZ1_a_2: C4_PZ1_a.2 R1_PZ1_a.1 U1_PZ1_a.6 U2_PZ1_a.12 | length 1387.8
  Top Layer w12: U1_PZ1_a.6@5863.79,6285.51 5863.22,6284.94 5863.22,6243.57 5863.79,6243 5863.79,6236.21 5925,6175 5925,6055 5957.8,6022.2 U2_PZ1_a.12@5996.22,6022.2
  Top Layer w15: C4_PZ1_a.2@5820.88,6670 5705,6670 5665.94,6630.94 5665.94,6450.94 5635,6420 5635,6210 5680,6165 5775,6165 5785,6175 5785,6196.21 5793.79,6205 5855.01,6205 5863.79,6213.79 U1_PZ1_a.6@5863.79,6285.51
  Top Layer w20: R1_PZ1_a.1@5820.88,6580 C4_PZ1_a.2@5820.88,6670
NetC4_PZ1_b_1: C4_PZ1_b.1 R1_PZ1_b.2 U1_PZ1_b.2 | length 218.6
  Top Layer w20: U1_PZ1_b.2@5911,5359.49 5911,5406 5931.12,5426.12 C4_PZ1_b.1@5931.12,5569.76
NetC4_PZ1_b_2: C4_PZ1_b.2 R1_PZ1_b.1 U1_PZ1_b.6 U2_PZ1_b.12 | length 1387.8
  Top Layer w12: U1_PZ1_b.6@5863.79,5170.51 5863.22,5169.94 5863.22,5128.57 5863.79,5128 5863.79,5121.21 5925,5060 5925,4940 5957.8,4907.2 U2_PZ1_b.12@5996.22,4907.2
  Top Layer w15: C4_PZ1_b.2@5820.88,5555 5705,5555 5665.94,5515.94 5665.94,5335.94 5635,5305 5635,5095 5680,5050 5775,5050 5785,5060 5785,5081.21 5793.79,5090 5855.01,5090 5863.79,5098.79 U1_PZ1_b.6@5863.79,5170.51
  Top Layer w20: R1_PZ1_b.1@5820.88,5465 C4_PZ1_b.2@5820.88,5555
NetC4_PZ1_c_1: C4_PZ1_c.1 R1_PZ1_c.2 U1_PZ1_c.2 | length 218.6
  Top Layer w20: U1_PZ1_c.2@5911,4244.49 5911,4291 5931.12,4311.12 C4_PZ1_c.1@5931.12,4454.76
NetC4_PZ1_c_2: C4_PZ1_c.2 R1_PZ1_c.1 U1_PZ1_c.6 U2_PZ1_c.12 | length 1387.8
  Top Layer w12: U1_PZ1_c.6@5863.79,4055.51 5863.22,4054.94 5863.22,4013.57 5863.79,4013 5863.79,4006.21 5925,3945 5925,3825 5957.8,3792.2 U2_PZ1_c.12@5996.22,3792.2
  Top Layer w15: C4_PZ1_c.2@5820.88,4440 5705,4440 5665.94,4400.94 5665.94,4220.94 5635,4190 5635,3980 5680,3935 5775,3935 5785,3945 5785,3966.21 5793.79,3975 5855.01,3975 5863.79,3983.79 5863.79,4006.21 U1_PZ1_c.6@5863.79,4055.51
  Top Layer w20: R1_PZ1_c.1@5820.88,4350 C4_PZ1_c.2@5820.88,4440
NetC4_PZ1_d_1: C4_PZ1_d.1 R1_PZ1_d.2 U1_PZ1_d.2 | length 218.6
  Top Layer w20: U1_PZ1_d.2@5911,3119.49 5911,3166 5931.12,3186.12 C4_PZ1_d.1@5931.12,3329.76
NetC4_PZ1_d_2: C4_PZ1_d.2 R1_PZ1_d.1 U1_PZ1_d.6 U2_PZ1_d.12 | length 1387.8
  Top Layer w12: U1_PZ1_d.6@5863.79,2930.51 5863.22,2929.94 5863.22,2888.57 5863.79,2888 5863.79,2881.21 5925,2820 5925,2700 5957.8,2667.2 U2_PZ1_d.12@5996.22,2667.2
  Top Layer w15: C4_PZ1_d.2@5820.88,3315 5705,3315 5665.94,3275.94 5665.94,3095.94 5635,3065 5635,2855 5680,2810 5775,2810 5785,2820 5785,2841.21 5793.79,2850 5855.01,2850 5863.79,2858.79 U1_PZ1_d.6@5863.79,2930.51
  Top Layer w20: R1_PZ1_d.1@5820.88,3225 C4_PZ1_d.2@5820.88,3315
NetC4_PZ2_a_1: C4_PZ2_a.1 R1_PZ2_a.2 U1_PZ2_a.2 | length 218.6
  Top Layer w20: U1_PZ2_a.2@6746,6474.49 6746,6521 6766.12,6541.12 C4_PZ2_a.1@6766.12,6684.76
NetC4_PZ2_a_2: C4_PZ2_a.2 R1_PZ2_a.1 U1_PZ2_a.6 U2_PZ2_a.12 | length 1387.8
  Top Layer w12: U1_PZ2_a.6@6698.79,6285.51 6698.22,6284.94 6698.22,6243.57 6698.79,6243 6698.79,6236.21 6760,6175 6760,6055 6792.8,6022.2 U2_PZ2_a.12@6831.22,6022.2
  Top Layer w15: C4_PZ2_a.2@6655.88,6670 6540,6670 6500.94,6630.94 6500.94,6450.94 6470,6420 6470,6210 6515,6165 6610,6165 6620,6175 6620,6196.21 6628.79,6205 6690.01,6205 6698.79,6213.79 U1_PZ2_a.6@6698.79,6285.51
  Top Layer w20: R1_PZ2_a.1@6655.88,6580 C4_PZ2_a.2@6655.88,6670
NetC4_PZ2_b_1: C4_PZ2_b.1 R1_PZ2_b.2 U1_PZ2_b.2 | length 218.6
  Top Layer w20: U1_PZ2_b.2@6746,5359.49 6746,5406 6766.12,5426.12 C4_PZ2_b.1@6766.12,5569.76
NetC4_PZ2_b_2: C4_PZ2_b.2 R1_PZ2_b.1 U1_PZ2_b.6 U2_PZ2_b.12 | length 1387.8
  Top Layer w12: U1_PZ2_b.6@6698.79,5170.51 6698.22,5169.94 6698.22,5128.57 6698.79,5128 6698.79,5121.21 6760,5060 6760,4940 6792.8,4907.2 U2_PZ2_b.12@6831.22,4907.2
  Top Layer w15: C4_PZ2_b.2@6655.88,5555 6540,5555 6500.94,5515.94 6500.94,5335.94 6470,5305 6470,5095 6515,5050 6610,5050 6620,5060 6620,5081.21 6628.79,5090 6690.01,5090 6698.79,5098.79 U1_PZ2_b.6@6698.79,5170.51
  Top Layer w20: R1_PZ2_b.1@6655.88,5465 C4_PZ2_b.2@6655.88,5555
NetC4_PZ2_c_1: C4_PZ2_c.1 R1_PZ2_c.2 U1_PZ2_c.2 | length 218.6
  Top Layer w20: U1_PZ2_c.2@6746,4244.49 6746,4291 6766.12,4311.12 C4_PZ2_c.1@6766.12,4454.76
NetC4_PZ2_c_2: C4_PZ2_c.2 R1_PZ2_c.1 U1_PZ2_c.6 U2_PZ2_c.12 | length 1387.8
  Top Layer w12: U1_PZ2_c.6@6698.79,4055.51 6698.22,4054.94 6698.22,4013.57 6698.79,4013 6698.79,4006.21 6760,3945 6760,3825 6792.8,3792.2 U2_PZ2_c.12@6831.22,3792.2
  Top Layer w15: C4_PZ2_c.2@6655.88,4440 6540,4440 6500.94,4400.94 6500.94,4220.94 6470,4190 6470,3980 6515,3935 6610,3935 6620,3945 6620,3966.21 6628.79,3975 6690.01,3975 6698.79,3983.79 U1_PZ2_c.6@6698.79,4055.51
  Top Layer w20: R1_PZ2_c.1@6655.88,4350 C4_PZ2_c.2@6655.88,4440
NetC4_PZ2_d_1: C4_PZ2_d.1 R1_PZ2_d.2 U1_PZ2_d.2 | length 218.6
  Top Layer w20: U1_PZ2_d.2@6746,3119.49 6746,3166 6766.12,3186.12 C4_PZ2_d.1@6766.12,3329.76
NetC4_PZ2_d_2: C4_PZ2_d.2 R1_PZ2_d.1 U1_PZ2_d.6 U2_PZ2_d.12 | length 1387.8
  Top Layer w12: U1_PZ2_d.6@6698.79,2930.51 6698.22,2929.94 6698.22,2888.57 6698.79,2888 6698.79,2881.21 6760,2820 6760,2700 6792.8,2667.2 U2_PZ2_d.12@6831.22,2667.2
  Top Layer w15: C4_PZ2_d.2@6655.88,3315 6540,3315 6500.94,3275.94 6500.94,3095.94 6470,3065 6470,2855 6515,2810 6610,2810 6620,2820 6620,2841.21 6628.79,2850 6690.01,2850 6698.79,2858.79 U1_PZ2_d.6@6698.79,2930.51
  Top Layer w20: R1_PZ2_d.1@6655.88,3225 C4_PZ2_d.2@6655.88,3315
NetC4_PZ3_a_1: C4_PZ3_a.1 R1_PZ3_a.2 U1_PZ3_a.2 | length 218.6
  Top Layer w20: U1_PZ3_a.2@7581,6474.49 7581,6521 7601.12,6541.12 C4_PZ3_a.1@7601.12,6684.76
NetC4_PZ3_a_2: C4_PZ3_a.2 R1_PZ3_a.1 U1_PZ3_a.6 U2_PZ3_a.12 | length 1387.8
  Top Layer w12: U1_PZ3_a.6@7533.79,6285.51 7533.22,6284.94 7533.22,6243.57 7533.79,6243 7533.79,6236.21 7595,6175 7595,6055 7627.8,6022.2 U2_PZ3_a.12@7666.22,6022.2
  Top Layer w15: C4_PZ3_a.2@7490.88,6670 7375,6670 7335.94,6630.94 7335.94,6450.94 7305,6420 7305,6210 7350,6165 7445,6165 7455,6175 7455,6196.21 7463.79,6205 7525.01,6205 7533.79,6213.79 U1_PZ3_a.6@7533.79,6285.51
  Top Layer w20: R1_PZ3_a.1@7490.88,6580 C4_PZ3_a.2@7490.88,6670
NetC4_PZ3_b_1: C4_PZ3_b.1 R1_PZ3_b.2 U1_PZ3_b.2 | length 218.6
  Top Layer w20: U1_PZ3_b.2@7581,5359.49 7581,5406 7601.12,5426.12 C4_PZ3_b.1@7601.12,5569.76
NetC4_PZ3_b_2: C4_PZ3_b.2 R1_PZ3_b.1 U1_PZ3_b.6 U2_PZ3_b.12 | length 1387.8
  Top Layer w12: U1_PZ3_b.6@7533.79,5170.51 7533.22,5169.94 7533.22,5128.57 7533.79,5128 7533.79,5121.21 7595,5060 7595,4940 7627.8,4907.2 U2_PZ3_b.12@7666.22,4907.2
  Top Layer w15: C4_PZ3_b.2@7490.88,5555 7375,5555 7335.94,5515.94 7335.94,5335.94 7305,5305 7305,5095 7350,5050 7445,5050 7455,5060 7455,5081.21 7463.79,5090 7525.01,5090 7533.79,5098.79 U1_PZ3_b.6@7533.79,5170.51
  Top Layer w20: R1_PZ3_b.1@7490.88,5465 C4_PZ3_b.2@7490.88,5555
NetC4_PZ3_c_1: C4_PZ3_c.1 R1_PZ3_c.2 U1_PZ3_c.2 | length 218.6
  Top Layer w20: U1_PZ3_c.2@7581,4244.49 7581,4291 7601.12,4311.12 C4_PZ3_c.1@7601.12,4454.76
NetC4_PZ3_c_2: C4_PZ3_c.2 R1_PZ3_c.1 U1_PZ3_c.6 U2_PZ3_c.12 | length 1389.5
  Top Layer w12: U1_PZ3_c.6@7533.79,4055.51 7533.22,4054.94 7533.22,4013.57 7533.79,4013 7533.79,4006.21 7595,3945 7595,3825 7627.8,3792.2 U2_PZ3_c.12@7666.22,3792.2
  Top Layer w15: C4_PZ3_c.2@7490.88,4440 7375,4440 7335.94,4400.94 7335.94,4220.94 7310,4195 7310,4080 7325,4065 7325,3950 7340,3935 7445,3935 7455,3945 7455,3966.21 7463.79,3975 7525.01,3975 7533.79,3983.79 U1_PZ3_c.6@7533.79,4055.51
  Top Layer w20: R1_PZ3_c.1@7490.88,4350 C4_PZ3_c.2@7490.88,4440
NetC4_PZ3_d_1: C4_PZ3_d.1 R1_PZ3_d.2 U1_PZ3_d.2 | length 218.6
  Top Layer w20: U1_PZ3_d.2@7581,3119.49 7581,3166 7601.12,3186.12 C4_PZ3_d.1@7601.12,3329.76
NetC4_PZ3_d_2: C4_PZ3_d.2 R1_PZ3_d.1 U1_PZ3_d.6 U2_PZ3_d.12 | length 1387.8
  Top Layer w12: U1_PZ3_d.6@7533.79,2930.51 7533.22,2929.94 7533.22,2888.57 7533.79,2888 7533.79,2881.21 7595,2820 7595,2700 7627.8,2667.2 U2_PZ3_d.12@7666.22,2667.2
  Top Layer w15: C4_PZ3_d.2@7490.88,3315 7375,3315 7335.94,3275.94 7335.94,3095.94 7305,3065 7305,2855 7350,2810 7445,2810 7455,2820 7455,2841.21 7463.79,2850 7525.01,2850 7533.79,2858.79 U1_PZ3_d.6@7533.79,2930.51
  Top Layer w20: R1_PZ3_d.1@7490.88,3225 C4_PZ3_d.2@7490.88,3315
NetC5_PZ1_a_1: C5_PZ1_a.1 R2_PZ1_a.1 | length 94.9
  Top Layer w20: R2_PZ1_a.1@5956.12,6770 C5_PZ1_a.1@6051,6770
NetC5_PZ1_b_1: C5_PZ1_b.1 R2_PZ1_b.1 | length 94.9
  Top Layer w20: R2_PZ1_b.1@5956.12,5655 C5_PZ1_b.1@6051,5655
NetC5_PZ1_c_1: C5_PZ1_c.1 R2_PZ1_c.1 | length 94.9
  Top Layer w20: R2_PZ1_c.1@5956.12,4540 C5_PZ1_c.1@6051,4540
NetC5_PZ1_d_1: C5_PZ1_d.1 R2_PZ1_d.1 | length 94.9
  Top Layer w20: R2_PZ1_d.1@5956.12,3415 C5_PZ1_d.1@6051,3415
NetC5_PZ2_a_1: C5_PZ2_a.1 R2_PZ2_a.1 | length 94.9
  Top Layer w20: R2_PZ2_a.1@6791.12,6770 C5_PZ2_a.1@6886,6770
NetC5_PZ2_b_1: C5_PZ2_b.1 R2_PZ2_b.1 | length 94.9
  Top Layer w20: R2_PZ2_b.1@6791.12,5655 C5_PZ2_b.1@6886,5655
NetC5_PZ2_c_1: C5_PZ2_c.1 R2_PZ2_c.1 | length 94.9
  Top Layer w20: R2_PZ2_c.1@6791.12,4540 C5_PZ2_c.1@6886,4540
NetC5_PZ2_d_1: C5_PZ2_d.1 R2_PZ2_d.1 | length 94.9
  Top Layer w20: R2_PZ2_d.1@6791.12,3415 C5_PZ2_d.1@6886,3415
NetC5_PZ3_a_1: C5_PZ3_a.1 R2_PZ3_a.1 | length 94.9
  Top Layer w20: R2_PZ3_a.1@7626.12,6770 C5_PZ3_a.1@7721,6770
NetC5_PZ3_b_1: C5_PZ3_b.1 R2_PZ3_b.1 | length 94.9
  Top Layer w20: R2_PZ3_b.1@7626.12,5655 C5_PZ3_b.1@7721,5655
NetC5_PZ3_c_1: C5_PZ3_c.1 R2_PZ3_c.1 | length 94.9
  Top Layer w20: R2_PZ3_c.1@7626.12,4540 C5_PZ3_c.1@7721,4540
NetC5_PZ3_d_1: C5_PZ3_d.1 R2_PZ3_d.1 | length 94.9
  Top Layer w20: R2_PZ3_d.1@7626.12,3415 C5_PZ3_d.1@7721,3415
NetC7_2: C7.2 U3.5 | length 105.5
  Top Layer w20: C7.2@5620,1740 U3.5@5620,1845.51
NetC10_2: C10.2 U4.5 | length 115.5
  Top Layer w20: C10.2@6830,1735 U4.5@6830,1850.51
NetC13_2: C13.2 U5.5 | length 100.6
  Top Layer w20: C13.2@5599.88,1040 5599.88,1140.39 U5.5@5600,1140.51
NetC16_2: C16.2 U6.5 | length 116.5
  Top Layer w20: C16.2@6844,1010 U6.5@6844,1126.51
NetC25_3dB_a_2: C25_3dB_a.2 U9_3dB_a.5 | length 111.1
  Top Layer w15: C25_3dB_a.2@5331.88,6399 C25_3dB_a.2@5335.88,6403
  Top Layer w20: U9_3dB_a.5@5226.49,6399 C25_3dB_a.2@5331.88,6399
NetC25_3dB_b_2: C25_3dB_b.2 U9_3dB_b.5 | length 111.1
  Top Layer w15: C25_3dB_b.2@5326.88,5309 C25_3dB_b.2@5330.88,5313
  Top Layer w20: U9_3dB_b.5@5221.49,5309 C25_3dB_b.2@5326.88,5309
NetC25_3dB_c_2: C25_3dB_c.2 U9_3dB_c.5 | length 111.1
  Top Layer w15: C25_3dB_c.2@5326.88,4174 C25_3dB_c.2@5330.88,4178
  Top Layer w20: U9_3dB_c.5@5221.49,4174 C25_3dB_c.2@5326.88,4174
NetC25_3dB_d_2: C25_3dB_d.2 U9_3dB_d.5 | length 111.1
  Top Layer w15: C25_3dB_d.2@5326.88,3079 C25_3dB_d.2@5330.88,3083
  Top Layer w20: U9_3dB_d.5@5221.49,3079 C25_3dB_d.2@5326.88,3079
NetC25_6dB_a_2: C25_6dB_a.2 U9_6dB_a.5 | length 111.1
  Top Layer w15: C25_6dB_a.2@4361.88,6399 C25_6dB_a.2@4365.88,6403
  Top Layer w20: U9_6dB_a.5@4256.49,6399 C25_6dB_a.2@4361.88,6399
NetC25_6dB_b_2: C25_6dB_b.2 U9_6dB_b.5 | length 111.1
  Top Layer w15: C25_6dB_b.2@4356.88,5309 C25_6dB_b.2@4360.88,5313
  Top Layer w20: U9_6dB_b.5@4251.49,5309 C25_6dB_b.2@4356.88,5309
NetC25_6dB_c_2: C25_6dB_c.2 U9_6dB_c.5 | length 111.1
  Top Layer w15: C25_6dB_c.2@4356.88,4174 C25_6dB_c.2@4360.88,4178
  Top Layer w20: U9_6dB_c.5@4251.49,4174 C25_6dB_c.2@4356.88,4174
NetC25_6dB_d_2: C25_6dB_d.2 U9_6dB_d.5 | length 111.1
  Top Layer w15: C25_6dB_d.2@4356.88,3079 C25_6dB_d.2@4360.88,3083
  Top Layer w20: U9_6dB_d.5@4251.49,3079 C25_6dB_d.2@4356.88,3079
NetC25_12dB_a_2: C25_12dB_a.2 U9_12dB_a.5 | length 111.1
  Top Layer w15: C25_12dB_a.2@3386.88,6399 C25_12dB_a.2@3390.88,6403
  Top Layer w20: U9_12dB_a.5@3281.49,6399 C25_12dB_a.2@3386.88,6399
NetC25_12dB_b_2: C25_12dB_b.2 U9_12dB_b.5 | length 111.1
  Top Layer w15: C25_12dB_b.2@3386.88,5309 C25_12dB_b.2@3390.88,5313
  Top Layer w20: U9_12dB_b.5@3281.49,5309 C25_12dB_b.2@3386.88,5309
NetC25_12dB_c_2: C25_12dB_c.2 U9_12dB_c.5 | length 111.1
  Top Layer w15: C25_12dB_c.2@3386.88,4174 C25_12dB_c.2@3390.88,4178
  Top Layer w20: U9_12dB_c.5@3281.49,4174 C25_12dB_c.2@3386.88,4174
NetC25_12dB_d_2: C25_12dB_d.2 U9_12dB_d.5 | length 111.1
  Top Layer w15: C25_12dB_d.2@3386.88,3079 C25_12dB_d.2@3390.88,3083
  Top Layer w20: U9_12dB_d.5@3281.49,3079 C25_12dB_d.2@3386.88,3079
NetC25_24dB_a_2: C25_24dB_a.2 U9_24dB_a.5 | length 111.1
  Top Layer w15: C25_24dB_a.2@2416.88,6399 C25_24dB_a.2@2420.88,6403
  Top Layer w20: U9_24dB_a.5@2311.49,6399 C25_24dB_a.2@2416.88,6399
NetC25_24dB_b_2: C25_24dB_b.2 U9_24dB_b.5 | length 111.1
  Top Layer w15: C25_24dB_b.2@2416.88,5309 C25_24dB_b.2@2420.88,5313
  Top Layer w20: U9_24dB_b.5@2311.49,5309 C25_24dB_b.2@2416.88,5309
NetC25_24dB_c_2: C25_24dB_c.2 U9_24dB_c.5 | length 111.1
  Top Layer w15: C25_24dB_c.2@2416.88,4174 C25_24dB_c.2@2420.88,4178
  Top Layer w20: U9_24dB_c.5@2311.49,4174 C25_24dB_c.2@2416.88,4174
NetC25_24dB_d_2: C25_24dB_d.2 U9_24dB_d.5 | length 111.1
  Top Layer w15: C25_24dB_d.2@2416.88,3079 C25_24dB_d.2@2420.88,3083
  Top Layer w20: U9_24dB_d.5@2311.49,3079 C25_24dB_d.2@2416.88,3079
NetC27_3dB_a_1: C27_3dB_a.1 R13_3dB_a.2 U8_3dB_a.12 U9_3dB_a.6 | length 1154.7
  Top Layer w12: 5316,6481 5316,6582.5 5324.09,6590.59 U8_3dB_a.12@5341.67,6590.59
  Top Layer w15: U9_3dB_a.6@5226.49,6449 5284,6449 5316,6481
  Top Layer w20: C27_3dB_a.1@4810.88,6573 R13_3dB_a.2@4810.88,6483 4746,6483 4711,6448 4711,6379 4765,6325 4975,6325 5000,6300 5083,6300 5131,6348 5131,6413 5167,6449 U9_3dB_a.6@5226.49,6449
NetC27_3dB_a_2: C27_3dB_a.2 R13_3dB_a.1 U9_3dB_a.2 | length 213
  Top Layer w20: C27_3dB_a.2@4921.12,6573 R13_3dB_a.1@4921.12,6483 4956,6483 4972,6499 U9_3dB_a.2@5037.51,6499
NetC27_3dB_b_1: C27_3dB_b.1 R13_3dB_b.2 U8_3dB_b.12 U9_3dB_b.6 | length 1154.7
  Top Layer w12: 5311,5391 5311,5492.5 5319.09,5500.59 U8_3dB_b.12@5336.67,5500.59
  Top Layer w15: U9_3dB_b.6@5221.49,5359 5279,5359 5311,5391
  Top Layer w20: C27_3dB_b.1@4805.88,5483 R13_3dB_b.2@4805.88,5393 4741,5393 4706,5358 4706,5289 4760,5235 4970,5235 4995,5210 5078,5210 5126,5258 5126,5323 5162,5359 U9_3dB_b.6@5221.49,5359
NetC27_3dB_b_2: C27_3dB_b.2 R13_3dB_b.1 U9_3dB_b.2 | length 213
  Top Layer w20: C27_3dB_b.2@4916.12,5483 R13_3dB_b.1@4916.12,5393 4951,5393 4967,5409 U9_3dB_b.2@5032.51,5409
NetC27_3dB_c_1: C27_3dB_c.1 R13_3dB_c.2 U8_3dB_c.12 U9_3dB_c.6 | length 1154.7
  Top Layer w12: 5311,4256 5311,4357.5 5319.09,4365.59 U8_3dB_c.12@5336.67,4365.59
  Top Layer w15: U9_3dB_c.6@5221.49,4224 5279,4224 5311,4256
  Top Layer w20: C27_3dB_c.1@4805.88,4348 R13_3dB_c.2@4805.88,4258 4741,4258 4706,4223 4706,4154 4760,4100 4970,4100 4995,4075 5078,4075 5126,4123 5126,4188 5162,4224 U9_3dB_c.6@5221.49,4224
NetC27_3dB_c_2: C27_3dB_c.2 R13_3dB_c.1 U9_3dB_c.2 | length 213
  Top Layer w20: C27_3dB_c.2@4916.12,4348 R13_3dB_c.1@4916.12,4258 4951,4258 4967,4274 U9_3dB_c.2@5032.51,4274
NetC27_3dB_d_1: C27_3dB_d.1 R13_3dB_d.2 U8_3dB_d.12 U9_3dB_d.6 | length 1154.7
  Top Layer w12: 5311,3161 5311,3262.5 5319.09,3270.59 U8_3dB_d.12@5336.67,3270.59
  Top Layer w15: U9_3dB_d.6@5221.49,3129 5279,3129 5311,3161
  Top Layer w20: C27_3dB_d.1@4805.88,3253 R13_3dB_d.2@4805.88,3163 4741,3163 4706,3128 4706,3059 4760,3005 4970,3005 4995,2980 5078,2980 5126,3028 5126,3093 5162,3129 U9_3dB_d.6@5221.49,3129
NetC27_3dB_d_2: C27_3dB_d.2 R13_3dB_d.1 U9_3dB_d.2 | length 213
  Top Layer w20: C27_3dB_d.2@4916.12,3253 R13_3dB_d.1@4916.12,3163 4951,3163 4967,3179 U9_3dB_d.2@5032.51,3179
NetC27_6dB_a_1: C27_6dB_a.1 R13_6dB_a.2 U8_6dB_a.12 U9_6dB_a.6 | length 1154.7
  Top Layer w12: 4346,6481 4346,6582.5 4354.09,6590.59 U8_6dB_a.12@4371.67,6590.59
  Top Layer w15: U9_6dB_a.6@4256.49,6449 4314,6449 4346,6481
  Top Layer w20: C27_6dB_a.1@3840.88,6573 R13_6dB_a.2@3840.88,6483 3776,6483 3741,6448 3741,6379 3795,6325 4005,6325 4030,6300 4113,6300 4161,6348 4161,6413 4197,6449 U9_6dB_a.6@4256.49,6449
NetC27_6dB_a_2: C27_6dB_a.2 R13_6dB_a.1 U9_6dB_a.2 | length 213
  Top Layer w20: C27_6dB_a.2@3951.12,6573 R13_6dB_a.1@3951.12,6483 3986,6483 4002,6499 U9_6dB_a.2@4067.51,6499
NetC27_6dB_b_1: C27_6dB_b.1 R13_6dB_b.2 U8_6dB_b.12 U9_6dB_b.6 | length 1154.7
  Top Layer w12: 4341,5391 4341,5492.5 4349.09,5500.59 U8_6dB_b.12@4366.67,5500.59
  Top Layer w15: U9_6dB_b.6@4251.49,5359 4309,5359 4341,5391
  Top Layer w20: C27_6dB_b.1@3835.88,5483 R13_6dB_b.2@3835.88,5393 3771,5393 3736,5358 3736,5289 3790,5235 4000,5235 4025,5210 4108,5210 4156,5258 4156,5323 4192,5359 U9_6dB_b.6@4251.49,5359
NetC27_6dB_b_2: C27_6dB_b.2 R13_6dB_b.1 U9_6dB_b.2 | length 213
  Top Layer w20: C27_6dB_b.2@3946.12,5483 R13_6dB_b.1@3946.12,5393 3981,5393 3997,5409 U9_6dB_b.2@4062.51,5409
NetC27_6dB_c_1: C27_6dB_c.1 R13_6dB_c.2 U8_6dB_c.12 U9_6dB_c.6 | length 1154.7
  Top Layer w12: 4341,4256 4341,4357.5 4349.09,4365.59 U8_6dB_c.12@4366.67,4365.59
  Top Layer w15: U9_6dB_c.6@4251.49,4224 4309,4224 4341,4256
  Top Layer w20: C27_6dB_c.1@3835.88,4348 R13_6dB_c.2@3835.88,4258 3771,4258 3736,4223 3736,4154 3790,4100 4000,4100 4025,4075 4108,4075 4156,4123 4156,4188 4192,4224 U9_6dB_c.6@4251.49,4224
NetC27_6dB_c_2: C27_6dB_c.2 R13_6dB_c.1 U9_6dB_c.2 | length 213
  Top Layer w20: C27_6dB_c.2@3946.12,4348 R13_6dB_c.1@3946.12,4258 3981,4258 3997,4274 U9_6dB_c.2@4062.51,4274
NetC27_6dB_d_1: C27_6dB_d.1 R13_6dB_d.2 U8_6dB_d.12 U9_6dB_d.6 | length 1154.7
  Top Layer w12: 4341,3161 4341,3262.5 4349.09,3270.59 U8_6dB_d.12@4366.67,3270.59
  Top Layer w15: U9_6dB_d.6@4251.49,3129 4309,3129 4341,3161
  Top Layer w20: C27_6dB_d.1@3835.88,3253 R13_6dB_d.2@3835.88,3163 3771,3163 3736,3128 3736,3059 3790,3005 4000,3005 4025,2980 4108,2980 4156,3028 4156,3093 4192,3129 U9_6dB_d.6@4251.49,3129
NetC27_6dB_d_2: C27_6dB_d.2 R13_6dB_d.1 U9_6dB_d.2 | length 213
  Top Layer w20: C27_6dB_d.2@3946.12,3253 R13_6dB_d.1@3946.12,3163 3981,3163 3997,3179 U9_6dB_d.2@4062.51,3179
NetC27_12dB_a_1: C27_12dB_a.1 R13_12dB_a.2 U8_12dB_a.12 U9_12dB_a.6 | length 1154.7
  Top Layer w12: 3371,6481 3371,6582.5 3379.09,6590.59 U8_12dB_a.12@3396.67,6590.59
  Top Layer w15: U9_12dB_a.6@3281.49,6449 3339,6449 3371,6481
  Top Layer w20: C27_12dB_a.1@2865.88,6573 R13_12dB_a.2@2865.88,6483 2801,6483 2766,6448 2766,6379 2820,6325 3030,6325 3055,6300 3138,6300 3186,6348 3186,6413 3222,6449 U9_12dB_a.6@3281.49,6449
NetC27_12dB_a_2: C27_12dB_a.2 R13_12dB_a.1 U9_12dB_a.2 | length 213
  Top Layer w20: C27_12dB_a.2@2976.12,6573 R13_12dB_a.1@2976.12,6483 3011,6483 3027,6499 U9_12dB_a.2@3092.51,6499
NetC27_12dB_b_1: C27_12dB_b.1 R13_12dB_b.2 U8_12dB_b.12 U9_12dB_b.6 | length 1154.7
  Top Layer w12: 3371,5391 3371,5492.5 3379.09,5500.59 U8_12dB_b.12@3396.67,5500.59
  Top Layer w15: U9_12dB_b.6@3281.49,5359 3339,5359 3371,5391
  Top Layer w20: C27_12dB_b.1@2865.88,5483 R13_12dB_b.2@2865.88,5393 2801,5393 2766,5358 2766,5289 2820,5235 3030,5235 3055,5210 3138,5210 3186,5258 3186,5323 3222,5359 U9_12dB_b.6@3281.49,5359
NetC27_12dB_b_2: C27_12dB_b.2 R13_12dB_b.1 U9_12dB_b.2 | length 213
  Top Layer w20: C27_12dB_b.2@2976.12,5483 R13_12dB_b.1@2976.12,5393 3011,5393 3027,5409 U9_12dB_b.2@3092.51,5409
NetC27_12dB_c_1: C27_12dB_c.1 R13_12dB_c.2 U8_12dB_c.12 U9_12dB_c.6 | length 1150.5
  Top Layer w12: 3371,4256 3371,4357.5 3379.09,4365.59 U8_12dB_c.12@3396.67,4365.59
  Top Layer w15: U9_12dB_c.6@3281.49,4224 3339,4224 3371,4256
  Top Layer w20: C27_12dB_c.1@2865.88,4348 R13_12dB_c.2@2865.88,4258 2801,4258 2766,4223 2766,4154 2820,4100 3030,4100 3050,4080 3143,4080 3186,4123 3186,4188 3222,4224 U9_12dB_c.6@3281.49,4224
NetC27_12dB_c_2: C27_12dB_c.2 R13_12dB_c.1 U9_12dB_c.2 | length 213
  Top Layer w20: C27_12dB_c.2@2976.12,4348 R13_12dB_c.1@2976.12,4258 3011,4258 3027,4274 U9_12dB_c.2@3092.51,4274
NetC27_12dB_d_1: C27_12dB_d.1 R13_12dB_d.2 U8_12dB_d.12 U9_12dB_d.6 | length 1154.7
  Top Layer w12: 3371,3161 3371,3262.5 3379.09,3270.59 U8_12dB_d.12@3396.67,3270.59
  Top Layer w15: U9_12dB_d.6@3281.49,3129 3339,3129 3371,3161
  Top Layer w20: C27_12dB_d.1@2865.88,3253 R13_12dB_d.2@2865.88,3163 2801,3163 2766,3128 2766,3059 2820,3005 3030,3005 3055,2980 3138,2980 3186,3028 3186,3093 3222,3129 U9_12dB_d.6@3281.49,3129
NetC27_12dB_d_2: C27_12dB_d.2 R13_12dB_d.1 U9_12dB_d.2 | length 213
  Top Layer w20: C27_12dB_d.2@2976.12,3253 R13_12dB_d.1@2976.12,3163 3011,3163 3027,3179 U9_12dB_d.2@3092.51,3179
NetC27_24dB_a_1: C27_24dB_a.1 R13_24dB_a.2 U8_24dB_a.12 U9_24dB_a.6 | length 1154.7
  Top Layer w12: 2401,6481 2401,6582.5 2409.09,6590.59 U8_24dB_a.12@2426.67,6590.59
  Top Layer w15: U9_24dB_a.6@2311.49,6449 2369,6449 2401,6481
  Top Layer w20: C27_24dB_a.1@1895.88,6573 R13_24dB_a.2@1895.88,6483 1831,6483 1796,6448 1796,6379 1850,6325 2060,6325 2085,6300 2168,6300 2216,6348 2216,6413 2252,6449 U9_24dB_a.6@2311.49,6449
NetC27_24dB_a_2: C27_24dB_a.2 R13_24dB_a.1 U9_24dB_a.2 | length 213
  Top Layer w20: C27_24dB_a.2@2006.12,6573 R13_24dB_a.1@2006.12,6483 2041,6483 2057,6499 U9_24dB_a.2@2122.51,6499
